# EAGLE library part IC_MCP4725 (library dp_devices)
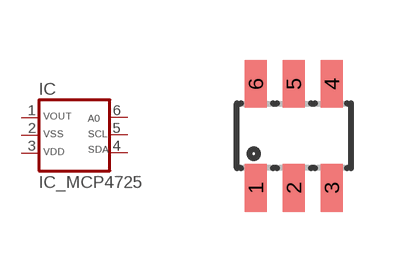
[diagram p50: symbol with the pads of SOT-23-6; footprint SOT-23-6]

Designator prefix IC

## IC_MCP4725  [SOT-23-6]
1  1  pas
2  2  pas
3  3  pas
4  4  pas
5  5  pas
6  6  pas

## Footprint SOT-23-6 (pad centres in mm)
smd 0.55 x 1.2: 1 -0.95,-1.3; 2 0,-1.3; 3 0.95,-1.3; 4 0.95,1.3; 5 0,1.3; 6 -0.95,1.3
